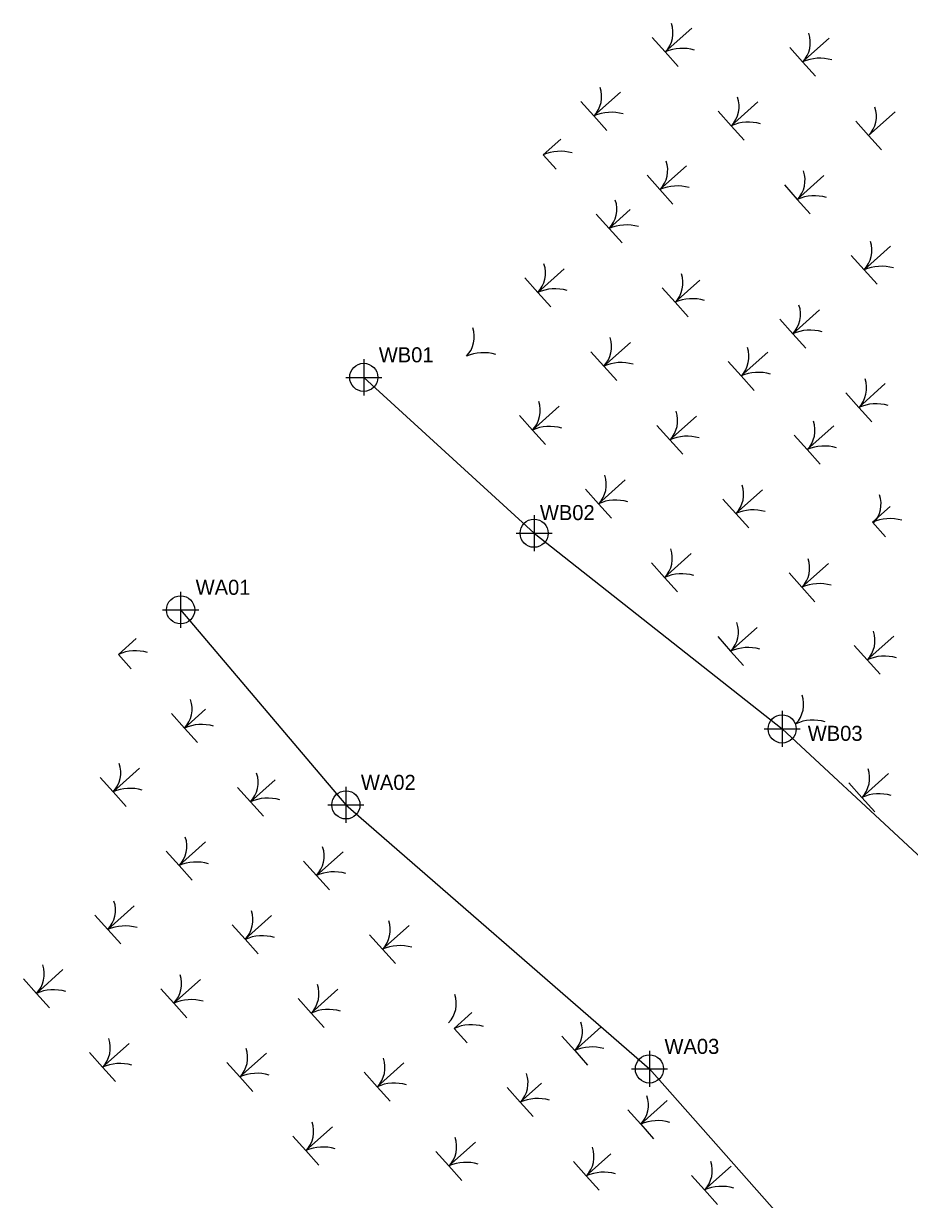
# Model space of a CAD drawing. Extents: x 2126502 to 2127032, y 149550 to 150101.
# Drawn here: x 2126501.7 to 2126649, y 149905.9 to 150101.5 of the extents above; entities that cross this region are included whole.
import ezdxf

# ---------------------------------------------------------------- set-up
doc = ezdxf.new("R2010")
doc.units = 0
for name, color, linetype in [('Exist Environmental Wetland Boundary', 7, 'Continuous'), ('Exist Environmental Wetland Boundary Cogo Number', 7, 'Continuous'), ('Exist Environmental Wetland Boundary Cogo Point CELL', 7, 'Continuous'), ('Exist Hydro Swamp or Marsh', 7, 'Continuous')]:
    doc.layers.add(name, color=color, linetype=linetype)

msp = doc.modelspace()

# ---------------------------------------------------------------- linework, layer by layer
at = {"layer": 'Exist Environmental Wetland Boundary'}
for points in [[(2126558.24, 150042.64), (2126586.56, 150016.72), (2126627.79, 149984.18), (2126669.56, 149945.39), (2126708.19, 149909.19), (2126734.44, 149881.64), (2126779.81, 149842.99), (2126804.06, 149818.21), (2126812.44, 149808.38)], [(2126527.8, 150003.98), (2126555.27, 149971.55), (2126605.73, 149927.65), (2126633.33, 149896.49), (2126619.48, 149877.19), (2126623.29, 149868.84), (2126639.28, 149883.08), (2126671.04, 149864.69), (2126726.71, 149808.11)]]:
    msp.add_lwpolyline(points, dxfattribs=at)
at = {"layer": 'Exist Environmental Wetland Boundary Cogo Point CELL'}
for points in [[(2126558.24, 150045.64), (2126558.24, 150042.64)], [(2126555.24, 150042.64), (2126558.24, 150042.64)], [(2126558.24, 150042.64), (2126561.24, 150042.64)], [(2126558.24, 150042.64), (2126558.24, 150039.64)], [(2126586.56, 150019.72), (2126586.56, 150016.72)], [(2126583.56, 150016.72), (2126586.56, 150016.72)], [(2126586.56, 150016.72), (2126589.56, 150016.72)], [(2126586.56, 150016.72), (2126586.56, 150013.72)], [(2126527.8, 150006.98), (2126527.8, 150003.98)], [(2126524.8, 150003.98), (2126527.8, 150003.98)], [(2126527.8, 150003.98), (2126530.8, 150003.98)], [(2126527.8, 150003.98), (2126527.8, 150000.98)], [(2126627.79, 149987.18), (2126627.79, 149984.18)], [(2126624.79, 149984.18), (2126627.79, 149984.18)], [(2126627.79, 149984.18), (2126630.79, 149984.18)], [(2126627.79, 149984.18), (2126627.79, 149981.18)], [(2126555.27, 149974.55), (2126555.27, 149971.55)], [(2126552.27, 149971.55), (2126555.27, 149971.55)], [(2126555.27, 149971.55), (2126558.27, 149971.55)], [(2126555.27, 149971.55), (2126555.27, 149968.55)], [(2126605.73, 149930.65), (2126605.73, 149927.65)], [(2126602.73, 149927.65), (2126605.73, 149927.65)], [(2126605.73, 149927.65), (2126608.73, 149927.65)], [(2126605.73, 149927.65), (2126605.73, 149924.65)]]:
    msp.add_lwpolyline(points, dxfattribs=at)
for centre in [(2126558.24, 150042.64), (2126586.56, 150016.72), (2126527.8, 150003.98), (2126627.79, 149984.18), (2126555.27, 149971.55), (2126605.73, 149927.65)]:
    msp.add_circle(centre, 2.34, dxfattribs=at)
at = {"layer": 'Exist Hydro Swamp or Marsh'}
for points in [[(2126606.2, 150099.14), (2126608.36, 150096.74), (2126612.76, 150100.69), (2126608.36, 150096.74), (2126610.51, 150094.33)], [(2126629.04, 150097.51), (2126631.19, 150095.1), (2126635.6, 150099.05), (2126631.19, 150095.1), (2126633.34, 150092.7)], [(2126594.35, 150088.52), (2126596.5, 150086.12), (2126600.91, 150090.06), (2126596.5, 150086.12), (2126598.65, 150083.71)], [(2126617.18, 150086.89), (2126619.33, 150084.48), (2126623.74, 150088.43), (2126619.33, 150084.48), (2126621.49, 150082.08)], [(2126640.01, 150085.25), (2126642.17, 150082.85), (2126646.57, 150086.8), (2126642.17, 150082.85), (2126644.32, 150080.45)], [(2126590.99, 150082.27), (2126588.05, 150079.63), (2126590.2, 150077.23)], [(2126605.33, 150076.26), (2126607.48, 150073.86), (2126611.89, 150077.81), (2126607.48, 150073.86), (2126609.63, 150071.46)], [(2126628.16, 150074.63), (2126630.31, 150072.23), (2126634.72, 150076.18), (2126630.31, 150072.23), (2126632.46, 150069.83)], [(2126596.87, 150069.78), (2126599.03, 150067.38), (2126602.55, 150070.53)], [(2126602.55, 150070.53), (2126599.03, 150067.38), (2126601.18, 150064.98)], [(2126639.26, 150062.92), (2126641.41, 150060.52), (2126645.82, 150064.46), (2126641.41, 150060.52), (2126643.57, 150058.11)], [(2126585.02, 150059.16), (2126587.17, 150056.76), (2126591.58, 150060.71), (2126587.17, 150056.76), (2126589.32, 150054.36)], [(2126607.85, 150057.53), (2126610, 150055.13), (2126614.1, 150058.8)], [(2126614.1, 150058.8), (2126610, 150055.13), (2126612.16, 150052.72)], [(2126627.41, 150052.3), (2126629.56, 150049.89), (2126633.97, 150053.84), (2126629.56, 150049.89), (2126631.71, 150047.49)], [(2126596, 150046.91), (2126598.15, 150044.5), (2126602.56, 150048.45), (2126598.15, 150044.5), (2126600.3, 150042.1)], [(2126618.83, 150045.28), (2126620.98, 150042.87), (2126625.39, 150046.82), (2126620.98, 150042.87), (2126623.13, 150040.47)], [(2126638.38, 150040.04), (2126640.54, 150037.64), (2126644.94, 150041.59), (2126640.54, 150037.64), (2126642.69, 150035.24)], [(2126584.14, 150036.29), (2126586.29, 150033.88), (2126590.7, 150037.83), (2126586.29, 150033.88), (2126588.44, 150031.48)], [(2126606.97, 150034.65), (2126609.12, 150032.25), (2126613.53, 150036.2), (2126609.12, 150032.25), (2126611.28, 150029.85)], [(2126629.81, 150033.02), (2126631.96, 150030.62), (2126636.37, 150034.57), (2126631.96, 150030.62), (2126634.11, 150028.22)], [(2126595.12, 150024.03), (2126597.27, 150021.63), (2126601.68, 150025.58), (2126597.27, 150021.63), (2126599.42, 150019.23)], [(2126617.95, 150022.4), (2126620.1, 150020), (2126624.51, 150023.95), (2126620.1, 150020), (2126622.25, 150017.6)], [(2126645.75, 150021.19), (2126642.81, 150018.55), (2126644.96, 150016.15)], [(2126606.09, 150011.78), (2126608.25, 150009.38), (2126612.65, 150013.33), (2126608.25, 150009.38), (2126610.4, 150006.97)], [(2126628.93, 150010.15), (2126631.08, 150007.74), (2126635.49, 150011.69), (2126631.08, 150007.74), (2126633.23, 150005.34)], [(2126617.07, 149999.53), (2126619.22, 149997.12), (2126623.63, 150001.07), (2126619.22, 149997.12), (2126621.38, 149994.72)], [(2126520.39, 149999.21), (2126517.45, 149996.58), (2126519.6, 149994.18)], [(2126639.78, 149998.08), (2126641.93, 149995.68), (2126646.34, 149999.63), (2126641.93, 149995.68), (2126644.08, 149993.28)], [(2126526.27, 149986.73), (2126528.43, 149984.32), (2126531.95, 149987.48)], [(2126531.95, 149987.48), (2126528.43, 149984.32), (2126530.58, 149981.92)], [(2126514.42, 149976.11), (2126516.57, 149973.7), (2126520.98, 149977.65), (2126516.57, 149973.7), (2126518.72, 149971.3)], [(2126638.9, 149975.21), (2126641.05, 149972.8), (2126645.46, 149976.75), (2126641.05, 149972.8), (2126643.2, 149970.4)], [(2126537.25, 149974.47), (2126539.4, 149972.07), (2126543.5, 149975.74)], [(2126543.5, 149975.74), (2126539.4, 149972.07), (2126541.56, 149969.67)], [(2126525.4, 149963.85), (2126527.55, 149961.45), (2126531.96, 149965.4), (2126527.55, 149961.45), (2126529.7, 149959.05)], [(2126548.23, 149962.22), (2126550.38, 149959.82), (2126554.79, 149963.77), (2126550.38, 149959.82), (2126552.53, 149957.42)], [(2126513.54, 149953.23), (2126515.69, 149950.83), (2126520.1, 149954.78), (2126515.69, 149950.83), (2126517.84, 149948.43)], [(2126536.37, 149951.6), (2126538.53, 149949.2), (2126542.93, 149953.15), (2126538.53, 149949.2), (2126540.68, 149946.79)], [(2126559.21, 149949.97), (2126561.36, 149947.56), (2126565.77, 149951.51), (2126561.36, 149947.56), (2126563.51, 149945.16)], [(2126501.68, 149942.61), (2126503.84, 149940.21), (2126508.24, 149944.16), (2126503.84, 149940.21), (2126505.99, 149937.81)], [(2126524.52, 149940.98), (2126526.67, 149938.58), (2126531.08, 149942.52), (2126526.67, 149938.58), (2126528.82, 149936.17)], [(2126547.35, 149939.35), (2126549.5, 149936.94), (2126553.91, 149940.89), (2126549.5, 149936.94), (2126551.65, 149934.54)], [(2126576.21, 149937.02), (2126573.28, 149934.39), (2126575.43, 149931.99)], [(2126591.15, 149933.1), (2126593.3, 149930.7), (2126597.71, 149934.65), (2126593.3, 149930.7), (2126595.45, 149928.3)], [(2126512.66, 149930.36), (2126514.81, 149927.95), (2126519.22, 149931.9), (2126514.81, 149927.95), (2126516.97, 149925.55)], [(2126535.49, 149928.72), (2126537.65, 149926.32), (2126542.05, 149930.27), (2126537.65, 149926.32), (2126539.8, 149923.92)], [(2126558.33, 149927.09), (2126560.48, 149924.69), (2126564.89, 149928.64), (2126560.48, 149924.69), (2126562.63, 149922.29)], [(2126582.1, 149924.54), (2126584.25, 149922.14), (2126587.77, 149925.29)], [(2126587.77, 149925.29), (2126584.25, 149922.14), (2126586.4, 149919.73)], [(2126602.13, 149920.85), (2126604.28, 149918.45), (2126608.69, 149922.4), (2126604.28, 149918.45), (2126606.43, 149916.04)], [(2126546.47, 149916.47), (2126548.62, 149914.07), (2126553.03, 149918.02), (2126548.62, 149914.07), (2126550.78, 149911.67)], [(2126570.24, 149913.92), (2126572.4, 149911.51), (2126576.8, 149915.46), (2126572.4, 149911.51), (2126574.55, 149909.11)], [(2126593.08, 149912.28), (2126595.23, 149909.88), (2126599.33, 149913.55)], [(2126599.33, 149913.55), (2126595.23, 149909.88), (2126597.38, 149907.48)], [(2126612.74, 149909.93), (2126614.89, 149907.53), (2126619.3, 149911.48), (2126614.89, 149907.53), (2126617.04, 149905.13)]]:
    msp.add_lwpolyline(points, dxfattribs=at)
for centre, radius, start, end in [((2126605.04, 150099.94), 4.61, 315.9957, 19.3903), ((2126627.87, 150098.31), 4.61, 315.9957, 19.3903), ((2126611.23, 150090.13), 7.21, 73.9828, 113.4775), ((2126634.06, 150088.49), 7.21, 73.9828, 113.4775), ((2126593.18, 150089.32), 4.61, 315.9957, 19.3903), ((2126616.02, 150087.69), 4.61, 315.9957, 19.3903), ((2126599.37, 150079.5), 7.21, 73.9828, 113.4775), ((2126638.85, 150086.06), 4.61, 315.9957, 19.3903), ((2126622.21, 150077.87), 7.21, 73.9828, 113.4775), ((2126590.92, 150073.02), 7.21, 73.9828, 113.4775), ((2126604.16, 150077.07), 4.61, 315.9957, 19.3903), ((2126626.99, 150075.43), 4.61, 315.9957, 19.3903), ((2126610.35, 150067.25), 7.21, 73.9828, 113.4775), ((2126633.18, 150065.62), 7.21, 73.9828, 113.4775), ((2126595.71, 150070.58), 4.61, 315.9957, 19.3903), ((2126601.9, 150060.77), 7.21, 73.9828, 113.4775), ((2126638.1, 150063.72), 4.61, 315.9957, 19.3903), ((2126583.85, 150059.96), 4.61, 315.9957, 19.3903), ((2126644.29, 150053.9), 7.21, 73.9828, 113.4775), ((2126606.69, 150058.33), 4.61, 315.9957, 19.3903), ((2126590.04, 150050.15), 7.21, 73.9828, 113.4775), ((2126612.88, 150048.51), 7.21, 73.9828, 113.4775), ((2126626.24, 150053.1), 4.61, 315.9957, 19.3903), ((2126572, 150049.34), 4.61, 315.9957, 19.3903), ((2126594.83, 150047.71), 4.61, 315.9957, 19.3903), ((2126632.43, 150043.28), 7.21, 73.9828, 113.4775), ((2126617.66, 150046.08), 4.61, 315.9957, 19.3903), ((2126578.19, 150039.53), 7.21, 73.9828, 113.4775), ((2126601.02, 150037.89), 7.21, 73.9828, 113.4775), ((2126623.85, 150036.26), 7.21, 73.9828, 113.4775), ((2126637.22, 150040.85), 4.61, 315.9957, 19.3903), ((2126582.97, 150037.09), 4.61, 315.9957, 19.3903), ((2126643.41, 150031.03), 7.21, 73.9828, 113.4775), ((2126605.81, 150035.46), 4.61, 315.9957, 19.3903), ((2126628.64, 150033.82), 4.61, 315.9957, 19.3903), ((2126589.16, 150027.27), 7.21, 73.9828, 113.4775), ((2126612, 150025.64), 7.21, 73.9828, 113.4775), ((2126634.83, 150024.01), 7.21, 73.9828, 113.4775), ((2126593.95, 150024.83), 4.61, 315.9957, 19.3903), ((2126616.78, 150023.2), 4.61, 315.9957, 19.3903), ((2126600.14, 150015.02), 7.21, 73.9828, 113.4775), ((2126639.62, 150021.57), 4.61, 315.9957, 19.3903), ((2126622.97, 150013.39), 7.21, 73.9828, 113.4775), ((2126645.68, 150011.94), 7.21, 73.9828, 113.4775), ((2126604.93, 150012.58), 4.61, 315.9957, 19.3903), ((2126627.76, 150010.95), 4.61, 315.9957, 19.3903), ((2126611.12, 150002.77), 7.21, 73.9828, 113.4775), ((2126633.95, 150001.13), 7.21, 73.9828, 113.4775), ((2126615.91, 150000.33), 4.61, 315.9957, 19.3903), ((2126638.61, 149998.88), 4.61, 315.9957, 19.3903), ((2126520.32, 149989.97), 7.21, 73.9828, 113.4775), ((2126622.09, 149990.51), 7.21, 73.9828, 113.4775), ((2126644.8, 149989.07), 7.21, 73.9828, 113.4775), ((2126525.11, 149987.53), 4.61, 315.9957, 19.3903), ((2126626.76, 149988.26), 4.61, 315.9957, 19.3903), ((2126531.3, 149977.71), 7.21, 73.9828, 113.4775), ((2126632.94, 149978.44), 7.21, 73.9828, 113.4775), ((2126513.25, 149976.91), 4.61, 315.9957, 19.3903), ((2126536.09, 149975.28), 4.61, 315.9957, 19.3903), ((2126637.73, 149976.01), 4.61, 315.9957, 19.3903), ((2126519.44, 149967.09), 7.21, 73.9828, 113.4775), ((2126643.92, 149966.19), 7.21, 73.9828, 113.4775), ((2126542.28, 149965.46), 7.21, 73.9828, 113.4775), ((2126524.23, 149964.65), 4.61, 315.9957, 19.3903), ((2126547.06, 149963.02), 4.61, 315.9957, 19.3903), ((2126530.42, 149954.84), 7.21, 73.9828, 113.4775), ((2126553.25, 149953.21), 7.21, 73.9828, 113.4775), ((2126512.37, 149954.03), 4.61, 315.9957, 19.3903), ((2126535.21, 149952.4), 4.61, 315.9957, 19.3903), ((2126518.56, 149944.22), 7.21, 73.9828, 113.4775), ((2126558.04, 149950.77), 4.61, 315.9957, 19.3903), ((2126541.4, 149942.58), 7.21, 73.9828, 113.4775), ((2126564.23, 149940.95), 7.21, 73.9828, 113.4775), ((2126500.52, 149943.41), 4.61, 315.9957, 19.3903), ((2126523.35, 149941.78), 4.61, 315.9957, 19.3903), ((2126546.19, 149940.15), 4.61, 315.9957, 19.3903), ((2126506.71, 149933.6), 7.21, 73.9828, 113.4775), ((2126569.02, 149938.52), 4.61, 315.9957, 19.3903), ((2126529.54, 149931.96), 7.21, 73.9828, 113.4775), ((2126552.37, 149930.33), 7.21, 73.9828, 113.4775), ((2126576.15, 149927.78), 7.21, 73.9828, 113.4775), ((2126589.98, 149933.9), 4.61, 315.9957, 19.3903), ((2126511.5, 149931.16), 4.61, 315.9957, 19.3903), ((2126534.33, 149929.53), 4.61, 315.9957, 19.3903), ((2126596.17, 149924.09), 7.21, 73.9828, 113.4775), ((2126517.69, 149921.34), 7.21, 73.9828, 113.4775), ((2126557.16, 149927.89), 4.61, 315.9957, 19.3903), ((2126540.52, 149919.71), 7.21, 73.9828, 113.4775), ((2126580.94, 149925.34), 4.61, 315.9957, 19.3903), ((2126563.35, 149918.08), 7.21, 73.9828, 113.4775), ((2126587.12, 149915.52), 7.21, 73.9828, 113.4775), ((2126600.96, 149921.65), 4.61, 315.9957, 19.3903), ((2126545.31, 149917.27), 4.61, 315.9957, 19.3903), ((2126607.15, 149911.84), 7.21, 73.9828, 113.4775), ((2126569.08, 149914.72), 4.61, 315.9957, 19.3903), ((2126551.5, 149907.46), 7.21, 73.9828, 113.4775), ((2126591.91, 149913.09), 4.61, 315.9957, 19.3903), ((2126575.27, 149904.9), 7.21, 73.9828, 113.4775), ((2126611.57, 149910.73), 4.61, 315.9957, 19.3903), ((2126598.1, 149903.27), 7.21, 73.9828, 113.4775), ((2126617.76, 149900.92), 7.21, 73.9828, 113.4775)]:
    msp.add_arc(centre, radius, start, end, dxfattribs=at)

# ---------------------------------------------------------------- texts
at = {"layer": 'Exist Environmental Wetland Boundary Cogo Number'}
for s, p in [('WB01', (2126560.74, 150045.14)), ('WB02', (2126587.52, 150018.9)), ('WA01', (2126530.3, 150006.48)), ('WB03', (2126632.05, 149982.2)), ('WA02', (2126557.77, 149974.05)), ('WA03', (2126608.23, 149930.15))]:
    msp.add_text(s, height=2.5, dxfattribs=at).set_placement(p)

doc.saveas('drawing.dxf')
